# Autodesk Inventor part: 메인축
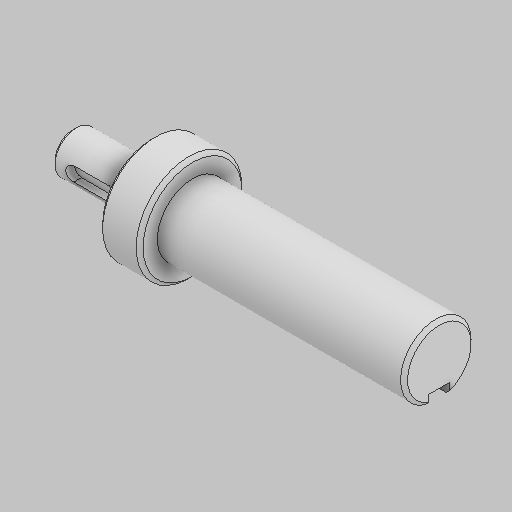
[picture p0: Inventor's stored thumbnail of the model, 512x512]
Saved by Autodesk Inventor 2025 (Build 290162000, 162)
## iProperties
Created: 2024-08
Part Number: 메인축
Material: 일반
Document SubType Name: Modeling
Designer: 현기
Density: 1 g/cm^3
Appearance: 기본값
Author: jhkim
Sending System: Autodesk Inventor 2025
Preprocessor: ST-DEVELOPER v20
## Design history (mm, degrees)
feature "솔리드1"
node "작업 평면1"
  node "작업축1"
node "솔리드2"
other parameters: "d0" = 15.70796
